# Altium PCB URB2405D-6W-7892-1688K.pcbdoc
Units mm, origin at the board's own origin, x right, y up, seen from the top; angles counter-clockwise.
Board outline 80 x 45 mm, 2 copper layers (Top Layer, Bottom Layer), stack 0.78 mm thick; 36 components, 14 nets, 83 pads, 139 vias.
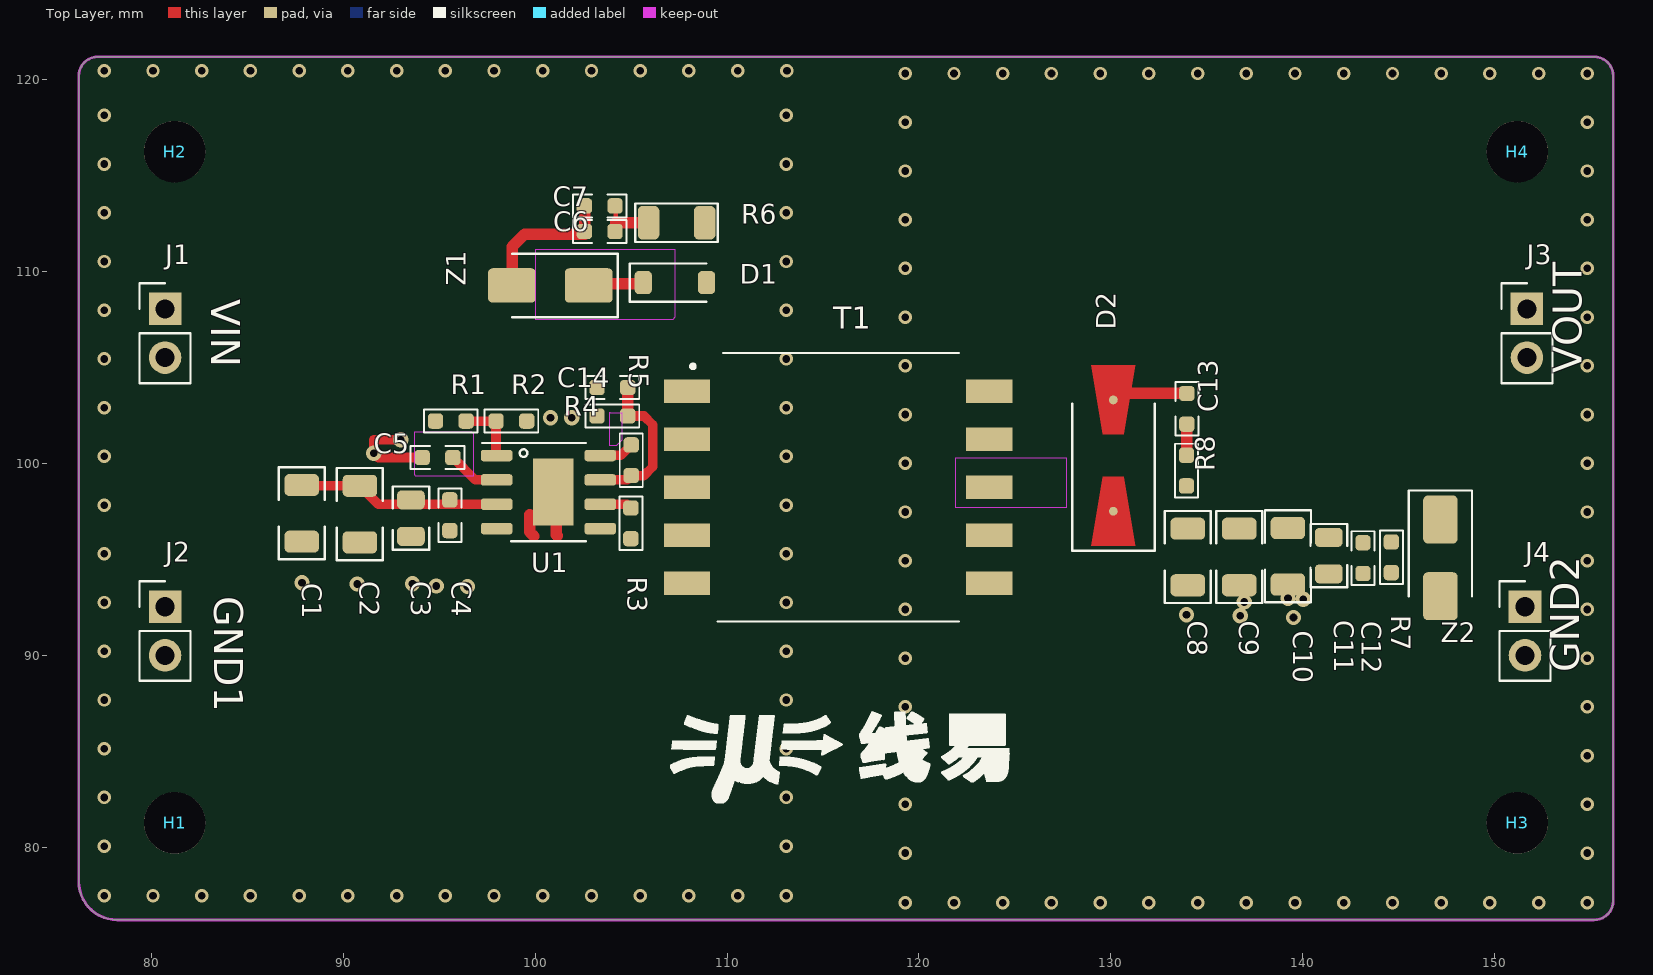
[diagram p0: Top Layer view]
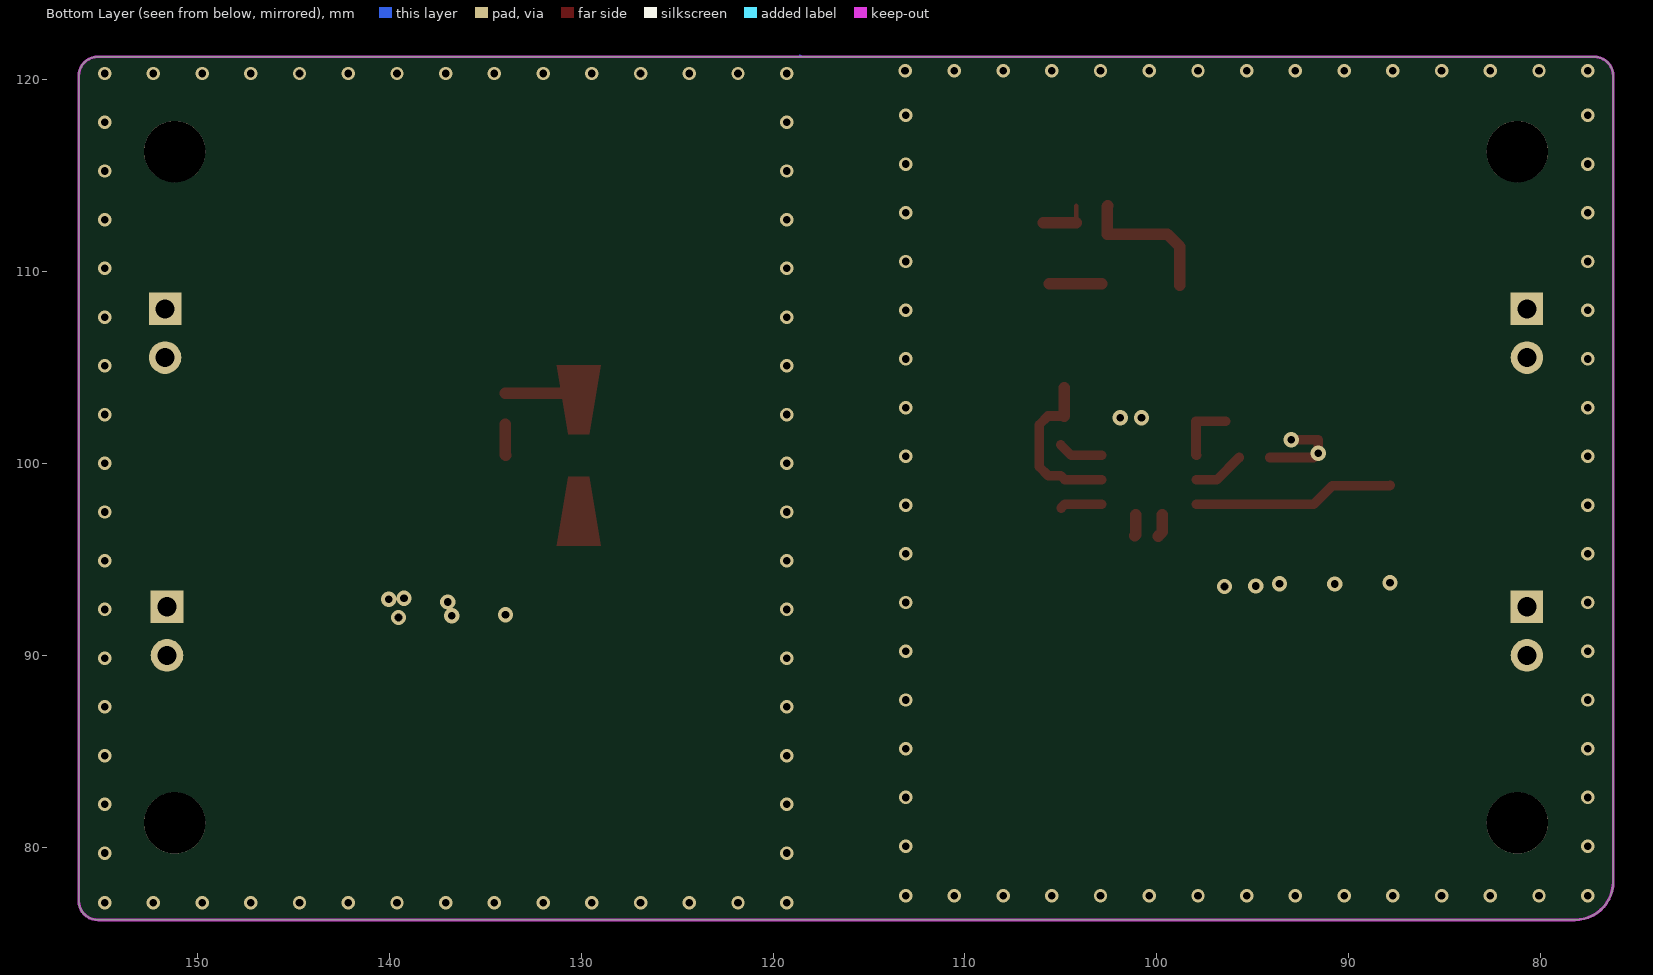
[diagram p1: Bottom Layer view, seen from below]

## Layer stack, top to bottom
Top Solder Mask Layer: solder mask 0.01, Dk 3.3
Top Layer: signal copper 0.035
Dielectric2: surface 0.71, FR4, Dk 4.5
Bottom Layer: signal copper 0.035
Bottom Solder Mask Layer: solder mask 0.01, Dk 3.3

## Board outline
76.2,120.2 cw(c77.2,120.2) 77.2,121.2 155.2,121.2 cw(c155.2,120.2) 156.2,120.2 156.2,77.2 cw(c155.2,77.2) 155.2,76.2 78.2,76.2 cw(c78.2,78.2) 76.2,78.2

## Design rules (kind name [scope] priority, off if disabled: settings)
BoardOutlineClearance copperThickness1oz [All] p0: genericclearance=0.254 ignorepadtopadclearanceinfootprint=FALSE except(0: Arc-SplitContinuation Track-SplitContinuation SMDPad-SplitContinuation THPad-SplitContinuation Via-SplitContinuation Fill-SplitContinuation Poly-SplitContinuation Region-SplitContinuation Text-SplitContinuation)
BoardOutlineClearance otherClearance [All] p0: genericclearance=0.254 ignorepadtopadclearanceinfootprint=FALSE except(0: Arc-SplitContinuation Track-SplitContinuation SMDPad-SplitContinuation THPad-SplitContinuation Via-SplitContinuation Fill-SplitContinuation Poly-SplitContinuation Region-SplitContinuation Text-SplitContinuation)
Clearance copperThickness1oz [All] p1: gap=0.178 ignorepadtopadclearanceinfootprint=FALSE
Clearance otherClearance [All] p1: gap=0.178 ignorepadtopadclearanceinfootprint=FALSE
DiffPairsRouting differentialPair [All] p1: maxuncoupledlength=10 minlimit=5 maxlimit=Infinity mostfreqgap=6 toplayer_minwidth=5 toplayer_prefwidth=100 toplayer_maxwidth=100 bottomlayer_minwidth=5 bottomlayer_prefwidth=100 bottomlayer_maxwidth=100
PasteMaskExpansion pasteMaskExpansion [All] p1: expansion=0
PlaneConnect innerPlane [All] p1: planeconnectstyle=Relief reliefexpansion=0.508 reliefentries=4 reliefconductorwidth=0.254 reliefairgap=0.254
PolygonConnect copper0 [All] p1: connectstyle=Direct reliefentries=4 reliefconductorwidth=10 polygonreliefangle="90 Angle" airgapwidth=10
PolygonConnect copper1 [All] p1: connectstyle=Direct reliefentries=4 reliefconductorwidth=10 polygonreliefangle="90 Angle" airgapwidth=10
RoutingVias viaSize [All] p1: viastyle="Through Hole" holewidth=24 minholewidth=11.811 maxholewidth=393.7 width=24 minwidth=11.811 maxwidth=393.7
SolderMaskExpansion solderMaskExpansion [All] p1: useseparateexpansions=TRUE expansion=2 expansionbottom=2
Width copperThickness1oz [All] p1: maxlimit=100 minlimit=5 preferedwidth=10

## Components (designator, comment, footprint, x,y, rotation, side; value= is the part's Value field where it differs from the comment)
C1 "MY_C" MYLibrary:C1206 87.825,97.396 r270 top
C2 "10uF" C1206 90.855,97.356 r270 top
C3 "MY_C" MYLibrary:C0805 93.515,97.146 r270 top
C4 "100nF" C0603 95.545,97.296 r90 top
C5 "1uF" C0603 94.905,100.306 r0 top
C6 "470pF" C0603 103.36,112.093 r180 top
C7 "My_library_C" MYLibrary:C0603 103.36,113.426 r180 top
C8 "100uF" C1206 134.02,95.121 r270 top
C9 "100uF" C1206 136.7,95.121 r270 top
C10 "100uF" C1206 139.24,95.156 r270 top
C11 "MY_C" MYLibrary:C0805 141.37,95.191 r270 top
C12 "100nF" C0603 143.15,95.061 r90 top
C13 "My_library_C" MYLibrary:C0603 133.97,102.846 r90 top
C14 "10pF" C0603 104.02,103.956 r0 top
D1 "DSS210" SOD-123_L2.8-W1.8-LS3.7-FD 107.279,109.426 r0 top
D2 "SS1060" SMC_L6.8-W5.9-LS7.8-RD 130.139,100.409 r90 top
H1 "Mechanical_MountingHole" MountingHole:MountingHole_3.2mm_M3_DIN965 81.2,81.256 r0 top
H2 "Mechanical_MountingHole" MountingHole:MountingHole_3.2mm_M3_DIN965 81.2,116.256 r0 top
H3 "Mechanical_MountingHole" MountingHole:MountingHole_3.2mm_M3_DIN965 151.2,81.256 r0 top
H4 "Mechanical_MountingHole" MountingHole:MountingHole_3.2mm_M3_DIN965 151.2,116.256 r0 top
J1 "HX PZ2.54-1x2P ZZ" HDR-TH_2P-P2.54-V-M-3 80.7,108.056 r0 top
J2 "HX PZ2.54-1x2P ZZ" HDR-TH_2P-P2.54-V-M-3 80.7,92.531 r0 top
J3 "HX PZ2.54-1x2P ZZ" HDR-TH_2P-P2.54-V-M-3 151.7,108.056 r0 top
J4 "HX PZ2.54-1x2P ZZ" HDR-TH_2P-P2.54-V-M-3 151.6,92.531 r0 top
R1 "100kΩ" R0603 95.595,102.206 r0 top
R2 "Device_R_Small" MYLibrary:R0603 98.755,102.206 r0 top
R3 "107kΩ" R0603 104.985,96.876 r270 top
R4 "10kΩ" R0603 104.02,102.471 r180 top
R5 "Device_R_Small" MYLibrary:R0603 105.005,100.166 r270 top
R6 "2.2kΩ" R1206 107.37,112.546 r180 top
R7 "330Ω" R0603 144.63,95.106 r90 top
R8 "Device_R_Small" MYLibrary:R0603 133.95,99.626 r90 top
T1 "" ? 115.788,98.758 r0 top
U1 "" coileasy:ESOP-8 100.802,98.25 r0 top
Z1 "1SMA5930A" SMA_L4.3-W2.6-LS5.2-RD 100.787,109.276 r180 top
Z2 "Diode_BZV55C75" Diode_SMD:D_SMA 147.19,95.076 r270 top

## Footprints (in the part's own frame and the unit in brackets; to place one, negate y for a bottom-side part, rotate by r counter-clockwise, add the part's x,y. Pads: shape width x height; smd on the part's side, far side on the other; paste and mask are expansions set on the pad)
C0603 [mm]
  rrect50% 0.8x0.8 smd: 1(-0.8,0) 2(0.8,0)
  silkscreen extent -1.4,-0.6 1.4,0.6
C1206 [mm]
  rrect43% 1.15x1.8 smd: 1(-1.475,0) 2(1.475,0)
  silkscreen extent -2.4,-1.2 2.4,1.2
coileasy:ESOP-8 [mm]
  rrect50% 1.65x0.6 smd: 1(-2.814,2.159) 2(-2.814,0.889) 3(-2.814,-0.381) 4(-2.814,-1.651) 5(2.586,-1.651) 6(2.586,-0.381) 7(2.586,0.889) 8(2.586,2.159)
  rect 2.1x3.5 smd: 9(0.136,0.254)
  silkscreen extent -3.56,-2.31 1.84,2.81
Diode_SMD:D_SMA [mm]
  rrect27% 2.5x1.8 smd: 1(-2,0) 2(2,0)
  silkscreen extent -3.51,-1.65 2,1.65
HDR-TH_2P-P2.54-V-M-3 [mm]
  rect 1.7x1.7 hole 1: 1(0,0)
  round 1.7 hole 1: 2(0,-2.54)
  silkscreen extent -1.33,-3.87 1.33,1.33
MountingHole:MountingHole_3.2mm_M3_DIN965 [mm]
  round 3.2 hole 3.2 unplated: ""(0,0)
MYLibrary:C0603 [mm]
  rrect50% 0.8x0.8 smd: 1(-0.8,0) 2(0.8,0)
  silkscreen extent -1.4,-0.6 1.4,0.6
MYLibrary:C0805 [mm]
  rrect50% 1x1.45 smd: 1(-0.95,0) 2(0.95,0)
  silkscreen extent -1.65,-0.95 1.65,0.96
MYLibrary:C1206 [mm]
  rrect43% 1.15x1.8 smd: 1(-1.475,0) 2(1.475,0)
  silkscreen extent -2.4,-1.2 2.4,1.2
MYLibrary:R0603 [mm]
  rrect50% 0.8x0.8 smd: 1(-0.8,0) 2(0.8,0)
  silkscreen extent -1.4,-0.6 1.4,0.6
R0603 [mm]
  rrect50% 0.8x0.8 smd: 1(-0.8,0) 2(0.8,0)
  silkscreen extent -1.4,-0.6 1.4,0.6
R1206 [mm]
  rrect44% 1.125x1.75 smd: 1(-1.462,0) 2(1.462,0)
  silkscreen extent -2.15,-1 2.15,1
SMA_L4.3-W2.6-LS5.2-RD [mm]
  rrect27% 2.5x1.8 smd: 1(-2,0) 2(2,0)
  silkscreen extent -3.51,-1.65 2,1.65
SMC_L6.8-W5.9-LS7.8-RD [mm]
  round 0.46 smd: 1(-2.9,0) 2(2.9,0)
  Top Layer region: -4.7,1.15 -4.7,-1.15 -1.1,-0.55 -1.1,0.55
  Top Layer region: 4.7,-1.15 4.7,1.15 1.1,0.55 1.1,-0.55
  silkscreen extent -4.96,-2.15 2.7,2.15
SOD-123_L2.8-W1.8-LS3.7-FD [mm]
  rrect50% 0.9x1.2 smd: 1(-1.65,0) 2(1.65,0)
  silkscreen extent -2.36,-1 1.65,1
? [mm]
  rect 2.4x1.22 smd: 1(-7.88,5) 2(-7.88,2.5) 3(-7.88,0) 4(-7.88,-2.5) 5(-7.88,-5) 6(7.88,-5) 7(7.88,-2.5) 8(7.88,0) 9(7.88,2.5) 10(7.88,5)
  silkscreen extent -7.62,-7 6.3,7

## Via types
v1: diameter 0.7, hole 0.4, Top Layer to Bottom Layer, 124 vias
v2: diameter 0.8, hole 0.4, Top Layer to Bottom Layer, 15 vias

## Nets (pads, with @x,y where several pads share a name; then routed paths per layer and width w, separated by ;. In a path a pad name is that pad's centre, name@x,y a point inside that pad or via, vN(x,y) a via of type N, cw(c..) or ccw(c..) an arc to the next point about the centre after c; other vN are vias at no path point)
$1N11: C6.1 C7.1 R6.2 | length 2.6
  Top Layer w0.25: 104.2,112.546 C7.1@104.2,113.426
  Top Layer w0.6: 104.2,112.546 R6.2
$1N16: C13.1 R8.2 | length 1.6
  Top Layer w0.6: R8.2 133.97,100.446 C13.1
$1N23: D1.1 Z1.1 | length 2.8
  Top Layer w0.25: Z1.1 Z1.1@102.878,109.366
  Top Layer w0.6: Z1.1@102.878,109.366 D1.1@105.6,109.366
$1N27: R5.1 U1.8 | length 2.4
  Top Layer w0.5: U1.8@102.875,100.416 104.455,100.416 R5.1
$1N29: C5.2 U1.2 | length 2.7
  Top Layer w0.5: C5.2 96.865,99.146 U1.2@97.925,99.146
$1N32: R3.1 U1.6 | length 2.2
  Top Layer w0.5: U1.6@102.875,97.876 104.785,97.876 R3.1
EN: R1.2 R2.1 U1.1 | length 3.4
  Top Layer w0.5: R1.2 R2.1 97.955,100.446 U1.1@97.925,100.416
GND1: C1.2 C2.2 C3.2 C4.1 C5.1 C14.1 J2.1 J2.2 R2.2 R4.2 U1.4 U1.9 | length 7
  Top Layer w0.5: v2(92.985,101.236) 91.585,101.236 v2(91.585,100.536) 91.815,100.306 C5.1
  Top Layer w0.6: 99.7,97.311 99.7,96.426 99.93,96.196 ; U1.9@101.1,97.311 101.1,96.286 101.15,96.236
  other v1: 77.53,77.456 80.07,77.456 82.61,77.456 85.15,77.456 87.69,77.456 90.23,77.456 92.77,77.456 95.31,77.456 97.85,77.456 100.39,77.456 102.93,77.456 105.47,77.456 108.01,77.456 110.55,77.456 113.09,77.456 77.53,80.046 113.09,80.046 77.53,82.586 113.09,82.586 77.53,85.126 113.09,85.126 77.53,87.666 113.09,87.666 77.53,90.206 113.09,90.206 77.53,92.746 113.09,92.746 77.53,95.286 113.09,95.286 77.53,97.826 113.09,97.826 77.53,100.366 113.09,100.366 77.53,102.906 113.09,102.906 77.53,105.446 113.09,105.446 77.53,107.986 113.09,107.986 77.53,110.526 113.09,110.526 77.53,113.066 113.09,113.066 77.53,115.606 113.09,115.606 77.53,118.146 113.09,118.146 77.53,120.475 80.07,120.475 82.61,120.475 85.15,120.475 87.69,120.475 90.23,120.475 92.77,120.475 95.31,120.475 97.85,120.475 100.39,120.475 102.93,120.475 105.47,120.475 108.01,120.475 110.55,120.475 113.121,120.475
  other v2: 96.465,93.586 94.835,93.606 90.715,93.716 93.6,93.726 87.835,93.786 100.795,102.376 101.895,102.376
GND2: C8.2 C9.2 C10.2 C11.2 C12.1 J4.1 J4.2 R7.1 T1.6 T1.7 Z2.2
  other v1: 119.29,77.096 121.83,77.096 124.37,77.096 126.91,77.096 129.45,77.096 131.99,77.096 134.53,77.096 137.07,77.096 139.61,77.096 142.15,77.096 144.69,77.096 147.23,77.096 149.77,77.096 152.31,77.096 154.85,77.096 119.29,79.686 154.85,79.686 119.29,82.226 154.85,82.226 119.29,84.766 154.85,84.766 119.29,87.306 154.85,87.306 119.29,89.846 154.85,89.846 119.29,92.386 154.85,92.386 119.29,94.926 154.85,94.926 119.29,97.466 154.85,97.466 119.29,100.006 154.85,100.006 119.29,102.546 154.85,102.546 119.29,105.086 154.85,105.086 119.29,107.626 154.85,107.626 119.29,110.166 154.85,110.166 119.29,112.706 154.85,112.706 119.29,115.246 154.85,115.246 119.29,117.786 154.85,117.786 119.29,120.326 121.83,120.326 124.37,120.326 126.91,120.326 129.45,120.326 131.99,120.326 134.53,120.326 137.07,120.326 139.61,120.326 142.15,120.326 144.69,120.326 147.23,120.326 149.77,120.326 152.31,120.326 154.85,120.326
  other v2: 139.53,91.966 136.75,92.056 133.95,92.106 136.97,92.776 140.045,92.916 139.24,92.966
RREF: C14.2 R4.1 R5.2 U1.7 | length 8.7
  Top Layer w0.5: U1.7@102.875,99.146 104.785,99.146 R5.2 105.665,99.366 106.125,99.826 106.125,102.016 105.67,102.471 R4.1
  Top Layer w0.6: R4.1 C14.2
SEC: C13.2 D2.2 T1.9 T1.10 | length 3.8
  Top Layer w0.6: 130.14,103.619 130.167,103.646 C13.2
SW: D1.2 R3.2 R6.1 T1.3 T1.4 U1.5
VIN: C1.1 C2.1 C3.1 C4.2 C6.2 C7.2 J1.1 J1.2 R1.1 T1.1 T1.2 U1.3 Z1.2 | length 18.1
  Top Layer w0.5: C1.1 87.865,98.831 C2.1 91.81,97.876 U1.3@97.925,97.876
  Top Layer w0.6: Z1.2 98.787,111.294 99.44,111.946 102.592,111.946 102.592,113.394 C7.2
VOUT: C8.1 C9.1 C10.1 C11.1 C12.2 D2.1 J3.1 J3.2 R7.2 R8.1 Z2.1
pads on no net: H1. H2. H3. H4. T1.5 T1.8

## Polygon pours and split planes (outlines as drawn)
GND2 on Bottom Layer (solid, remove dead copper, pour order 22): 118.542,121.256 118.6,121.256 118.6,121.314
GND2 on Bottom Layer (solid, remove dead copper, pour order 24): 118.6,121.256 156.2,121.256 156.2,76.256 118.6,76.256
SW on Top Layer (solid, remove dead copper, pour order 28): 106.87,99.366 109.64,99.366 109.895,99.626 109.895,105.516 107.395,108.016 107.395,112.866 107.955,113.426 110.368,113.426 111.505,112.289 111.505,96.286 110.595,95.376 102.14,95.376 101.9,95.616 101.9,96.816 101.96,96.876 106.165,96.876 106.87,97.846
SEC on Top Layer (solid, remove dead copper, pour order 30): 122.31,106.126 131.88,106.126 131.88,100.466 122.31,100.466
GND1 on Top Layer (solid, remove dead copper, pour order 32): 99.195,104.456 103.895,104.456 103.895,101.276 101.895,101.276 101.695,101.076 101.695,100.251 101.505,100.061 101.505,99.336 101.445,99.276 99.695,99.276 99.295,99.676 99.295,100.026 99.195,100.126
GND1 on Top Layer (solid, remove dead copper, pour order 34): 90.985,101.736 93.705,101.736 93.705,99.806 90.985,99.806
VIN on Top Layer (solid, remove dead copper, pour order 36): 78.9,111.066 109.358,111.066 109.358,97.586 78.9,97.586
GND2 on Top Layer (solid, remove dead copper, pour order 38): 122.16,97.186 126.39,97.186 126.39,90.596 122.16,90.596
GND1 on Top Layer (solid, remove dead copper, pour order 40): 76.2,121.256 113.858,121.256 113.858,76.256 76.2,76.256
GND1 on Bottom Layer (solid, remove dead copper, pour order 38): 76.2,121.256 113.858,121.256 113.858,76.256 76.2,76.256
GND2 on Top Layer (solid, remove dead copper, pour order 42): 118.542,121.219 156.2,121.219 156.2,76.256 118.542,76.256
VOUT on Top Layer (solid, remove dead copper, pour order 26): 127.997,100.087 132.104,100.087 132.298,100.282 145.506,100.282 148.3,103.076 148.3,109.172 148.83,109.702 153.343,109.702 153.343,95.586 127.997,95.586

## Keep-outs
Top Layer:
  region: 103.88,102.646 103.89,102.646 103.89,102.656
  region: 103.89,102.646 104.52,102.646 104.52,101.216 104.23,100.926 103.89,100.926
  region: 93.755,99.356 96.785,99.356 96.785,101.536 96.685,101.636 93.685,101.636 93.685,99.426
  region: 100.037,111.156 107.267,111.156 107.267,107.609 107.155,107.496 101.72,107.496 100.037,107.496
  region: 127.67,100.296 127.67,97.676 121.93,97.676 121.93,100.296
Board Outline Layer:
  the board outline again, w0.15

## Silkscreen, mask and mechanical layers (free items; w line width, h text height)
Top Silkscreen Layer:
  drawing of 9 lines, arcs and shapes, not listed
  text "VIN" at 83.1,108.566 h1.5 r270
  text "VOUT" at 154.547,104.692 h1.5 r90
  text "GND1" at 83.26,93.08 h1.5 r270
  text "GND2" at 154.437,89.112 h1.5 r90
